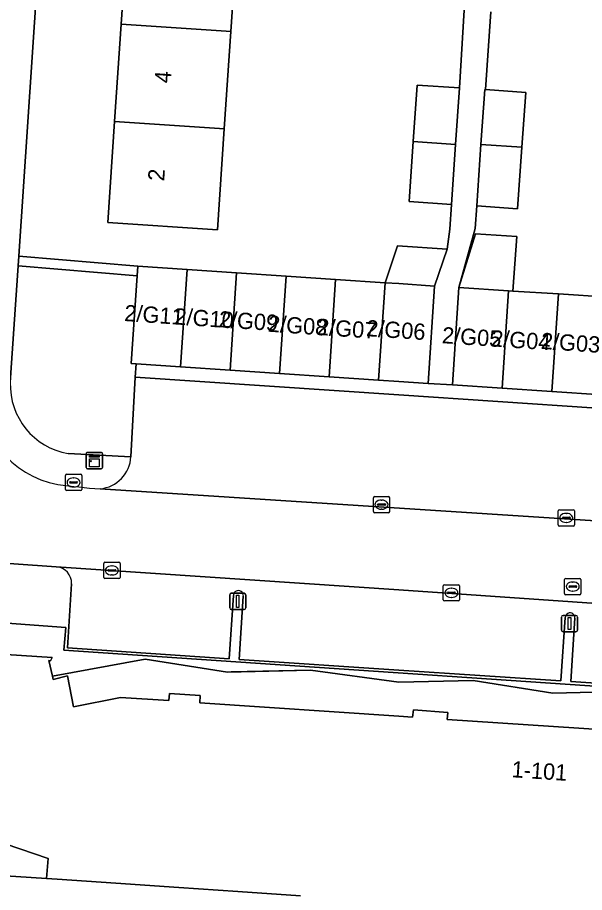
# Model space of a CAD drawing. Extents: x 161848 to 162726, y 385382 to 386521.
# Drawn here: x 161976.6 to 162011.4, y 386115.6 to 386169.4 of the extents above; entities that cross this region are included whole.
import ezdxf

# ---------------------------------------------------------------- set-up
doc = ezdxf.new("R2010")
doc.units = 0
for name, color, linetype in [('IMGEO_Erf', 7, 'Continuous'), ('IMGEO_Groenvoorziening', 7, 'Continuous'), ('IMGEO_Haag', 7, 'Continuous'), ('IMGEO_Kast', 7, 'Continuous'), ('IMGEO_Kolk', 7, 'Continuous'), ('IMGEO_Lichtmast', 7, 'Continuous'), ('IMGEO_Pand', 7, 'Continuous'), ('IMGEO_Pand_nummerreeks', 7, 'Continuous'), ('IMGEO_Pand_overbouw', 7, 'Continuous'), ('IMGEO_Parkeervlak_open', 7, 'Continuous'), ('IMGEO_Rijbaan_lokaal_open', 7, 'Continuous'), ('IMGEO_Rioolput', 7, 'Continuous'), ('IMGEO_Voetpad_open', 7, 'Continuous')]:
    doc.layers.add(name, color=color, linetype=linetype)

msp = doc.modelspace()

# ---------------------------------------------------------------- linework, layer by layer
at = {"layer": 'IMGEO_Erf'}
for points in [[(161981.585, 386228.399), (161976.646, 386154.728), (161983.951, 386154.112), (161986.99, 386153.908), (161990.03, 386153.703), (161993.069, 386153.499), (161996.108, 386153.295), (161999.148, 386153.09), (161999.91, 386155.357), (162002.957, 386155.152), (162003.129, 386156.382), (162003.232, 386157.9), (162000.629, 386158.077), (162000.88, 386161.759), (162001.117, 386165.23), (162003.72, 386165.053), (162004.011, 386169.831)], [(162005.647, 386169.739), (162005.314, 386164.953), (162007.786, 386164.781), (162007.553, 386161.42), (162007.291, 386157.629), (162004.777, 386157.804), (162004.681, 386156.415), (162003.684, 386152.798), (162004.707, 386156.103), (162007.247, 386155.936), (162006.991, 386152.581), (162009.79, 386152.398), (162012.842, 386152.199), (162015.895, 386151.999), (162018.948, 386151.799), (162023.139, 386151.525), (162033.95, 386150.87), (162035.725, 386178.438)], [(161990.074, 386174.523), (161989.672, 386168.529), (161989.271, 386162.535), (161988.856, 386156.345), (161982.121, 386156.796), (161982.536, 386162.985), (161982.937, 386168.979), (161983.339, 386174.973)]]:
    msp.add_lwpolyline(points, dxfattribs=at)
at = {"layer": 'IMGEO_Groenvoorziening'}
msp.add_lwpolyline([(161983.951, 386154.112), (161976.646, 386154.728), (161976.606, 386154.129), (161983.911, 386153.513)], close=True, dxfattribs=at)
for points in [[(161983.911, 386153.513), (161976.606, 386154.129), (161976.126, 386146.967)], [(161979.683, 386142.598), (161983.537, 386142.393), (161983.794, 386147.293), (161983.861, 386148.104), (161983.547, 386148.125), (161983.911, 386153.513)]]:
    msp.add_lwpolyline(points, dxfattribs=at)
msp.add_arc((161980.404, 386146.818), 4.281, 178.0004, 260.3007, dxfattribs=at)
at = {"layer": 'IMGEO_Haag'}
msp.add_lwpolyline([(161983.951, 386154.112), (161976.646, 386154.728), (161976.606, 386154.129), (161983.911, 386153.513)], close=True, dxfattribs=at)
at = {"layer": 'IMGEO_Kast'}
for p, q in [((161980.864, 386142.663), (161981.705, 386142.663)), ((161981.705, 386142.663), (161980.864, 386142.663)), ((161980.789, 386141.738), (161980.789, 386142.579)), ((161980.789, 386142.579), (161980.789, 386141.738)), ((161981.789, 386142.588), (161981.789, 386141.747)), ((161981.789, 386141.747), (161981.789, 386142.588)), ((161981.714, 386141.663), (161980.873, 386141.663)), ((161980.873, 386141.663), (161981.714, 386141.663))]:
    msp.add_line(p, q, dxfattribs=at)
for points in [[(161980.984, 386142.453), (161981.584, 386142.453), (161981.584, 386142.368), (161980.984, 386142.368), (161980.984, 386142.453)], [(161980.984, 386142.278), (161981.584, 386142.278), (161981.584, 386141.789), (161980.984, 386141.789), (161980.984, 386142.278)]]:
    msp.add_lwpolyline(points, dxfattribs=at)
msp.add_circle((161981.068, 386142.127), 0.0377, dxfattribs=at)
for centre, start, end in [((161980.867, 386142.585), 92.4484, 184.2845), ((161980.867, 386142.585), 92.4484, 184.2845), ((161981.711, 386142.585), 2.4484, 94.2845), ((161981.711, 386142.585), 2.4484, 94.2845), ((161980.867, 386141.741), 182.4484, 274.2845), ((161980.867, 386141.741), 182.4484, 274.2845), ((161981.711, 386141.741), 272.4484, 4.2845), ((161981.711, 386141.741), 272.4484, 4.2845)]:
    msp.add_arc(centre, 0.0779, start, end, dxfattribs=at)
at = {"layer": 'IMGEO_Kolk'}
for p, q in [((161979.513, 386140.395), (161979.513, 386141.247)), ((161979.588, 386141.321), (161980.44, 386141.321)), ((161980.001, 386141.101), (161980.026, 386141.101)), ((161980.514, 386141.247), (161980.514, 386140.395)), ((161979.772, 386140.815), (161979.772, 386140.827)), ((161980.21, 386140.778), (161979.812, 386140.778)), ((161979.815, 386140.864), (161980.213, 386140.864)), ((161980.024, 386140.541), (161979.999, 386140.541)), ((161980.256, 386140.827), (161980.256, 386140.815)), ((161980.44, 386140.321), (161979.588, 386140.321)), ((161998.428, 386139.032), (161998.428, 386139.884)), ((161998.503, 386139.958), (161999.355, 386139.958)), ((161998.687, 386139.452), (161998.687, 386139.464)), ((161998.73, 386139.501), (161999.128, 386139.501)), ((161998.916, 386139.738), (161998.941, 386139.738)), ((161999.171, 386139.464), (161999.171, 386139.452)), ((161999.429, 386139.884), (161999.429, 386139.032)), ((161999.355, 386138.958), (161998.503, 386138.958)), ((161999.125, 386139.415), (161998.727, 386139.415)), ((161998.939, 386139.178), (161998.914, 386139.178)), ((162009.778, 386138.215), (162009.778, 386139.067)), ((162009.853, 386139.141), (162010.705, 386139.141)), ((162010.266, 386138.921), (162010.291, 386138.921)), ((162010.779, 386139.067), (162010.779, 386138.215)), ((162010.037, 386138.635), (162010.037, 386138.647)), ((162010.475, 386138.598), (162010.077, 386138.598)), ((162010.08, 386138.684), (162010.478, 386138.684)), ((162010.289, 386138.361), (162010.264, 386138.361)), ((162010.521, 386138.647), (162010.521, 386138.635)), ((162010.705, 386138.141), (162009.853, 386138.141)), ((161981.866, 386134.989), (161981.866, 386135.841)), ((161981.941, 386135.915), (161982.793, 386135.915)), ((161982.354, 386135.695), (161982.379, 386135.695)), ((161982.867, 386135.841), (161982.867, 386134.989)), ((161982.125, 386135.409), (161982.125, 386135.421)), ((161982.563, 386135.372), (161982.165, 386135.372)), ((161982.168, 386135.458), (161982.566, 386135.458)), ((161982.377, 386135.135), (161982.352, 386135.135)), ((161982.609, 386135.421), (161982.609, 386135.409)), ((161982.793, 386134.915), (161981.941, 386134.915)), ((162002.721, 386133.614), (162002.721, 386134.466)), ((162002.796, 386134.54), (162003.648, 386134.54)), ((162003.023, 386134.083), (162003.421, 386134.083)), ((162003.209, 386134.32), (162003.234, 386134.32)), ((162003.722, 386134.466), (162003.722, 386133.614)), ((162003.648, 386133.54), (162002.796, 386133.54)), ((162002.98, 386134.034), (162002.98, 386134.046)), ((162003.418, 386133.997), (162003.02, 386133.997)), ((162003.232, 386133.76), (162003.207, 386133.76)), ((162003.464, 386134.046), (162003.464, 386134.034))]:
    msp.add_line(p, q, dxfattribs=at)
for points in [[(161979.513, 386140.395), (161979.513, 386141.247)], [(161979.588, 386141.321), (161980.44, 386141.321)], [(161980.514, 386141.247), (161980.514, 386140.395)], [(161980.44, 386140.321), (161979.588, 386140.321)], [(161998.428, 386139.032), (161998.428, 386139.884)], [(161998.503, 386139.958), (161999.355, 386139.958)], [(161999.429, 386139.884), (161999.429, 386139.032)], [(161999.355, 386138.958), (161998.503, 386138.958)], [(162009.778, 386138.215), (162009.778, 386139.067)], [(162009.853, 386139.141), (162010.705, 386139.141)], [(162010.779, 386139.067), (162010.779, 386138.215)], [(162010.705, 386138.141), (162009.853, 386138.141)], [(161981.866, 386134.989), (161981.866, 386135.841)], [(161981.941, 386135.915), (161982.793, 386135.915)], [(161982.867, 386135.841), (161982.867, 386134.989)], [(161982.793, 386134.915), (161981.941, 386134.915)], [(162002.721, 386133.614), (162002.721, 386134.466)], [(162002.796, 386134.54), (162003.648, 386134.54)], [(162003.722, 386134.466), (162003.722, 386133.614)], [(162003.648, 386133.54), (162002.796, 386133.54)]]:
    msp.add_lwpolyline(points, dxfattribs=at)
for centre, radius, start, end in [((161979.59, 386141.245), 0.0765, 91.552, 178.448), ((161979.59, 386141.245), 0.0765, 91.552, 178.448), ((161980.438, 386141.245), 0.0765, 1.552, 88.448), ((161980.438, 386141.245), 0.0765, 1.552, 88.448), ((161979.812, 386140.824), 0.0403, 85.8775, 175.7526), ((161979.809, 386140.814), 0.0366, 178.938, 274.7102), ((161980.213, 386140.821), 0.043, 264.8664, 352.4533), ((161980.217, 386140.826), 0.0386, 1.7309, 96.639), ((161979.59, 386140.397), 0.0765, 181.552, 268.448), ((161979.59, 386140.397), 0.0765, 181.552, 268.448), ((161980.438, 386140.397), 0.0765, 271.552, 358.448), ((161980.438, 386140.397), 0.0765, 271.552, 358.448), ((161998.505, 386139.882), 0.0765, 91.552, 178.448), ((161998.505, 386139.882), 0.0765, 91.552, 178.448), ((161998.727, 386139.461), 0.0403, 85.8775, 175.7526), ((161998.724, 386139.451), 0.0366, 178.938, 274.7102), ((161999.128, 386139.458), 0.043, 264.8664, 352.4533), ((161999.132, 386139.463), 0.0386, 1.7309, 96.639), ((161999.353, 386139.882), 0.0765, 1.552, 88.448), ((161999.353, 386139.882), 0.0765, 1.552, 88.448), ((161998.505, 386139.034), 0.0765, 181.552, 268.448), ((161998.505, 386139.034), 0.0765, 181.552, 268.448), ((161999.353, 386139.034), 0.0765, 271.552, 358.448), ((161999.353, 386139.034), 0.0765, 271.552, 358.448), ((162009.855, 386139.065), 0.0765, 91.552, 178.448), ((162009.855, 386139.065), 0.0765, 91.552, 178.448), ((162010.703, 386139.065), 0.0765, 1.552, 88.448), ((162010.703, 386139.065), 0.0765, 1.552, 88.448), ((162010.077, 386138.644), 0.0403, 85.8775, 175.7526), ((162010.074, 386138.634), 0.0366, 178.938, 274.7102), ((162010.478, 386138.641), 0.043, 264.8664, 352.4533), ((162010.482, 386138.646), 0.0386, 1.7309, 96.639), ((162009.855, 386138.217), 0.0765, 181.552, 268.448), ((162009.855, 386138.217), 0.0765, 181.552, 268.448), ((162010.703, 386138.217), 0.0765, 271.552, 358.448), ((162010.703, 386138.217), 0.0765, 271.552, 358.448), ((161981.943, 386135.839), 0.0765, 91.552, 178.448), ((161981.943, 386135.839), 0.0765, 91.552, 178.448), ((161982.791, 386135.839), 0.0765, 1.552, 88.448), ((161982.791, 386135.839), 0.0765, 1.552, 88.448), ((161982.165, 386135.418), 0.0403, 85.8775, 175.7526), ((161982.162, 386135.408), 0.0366, 178.938, 274.7102), ((161982.566, 386135.415), 0.043, 264.8664, 352.4533), ((161982.57, 386135.42), 0.0386, 1.7309, 96.639), ((161981.943, 386134.991), 0.0765, 181.552, 268.448), ((161981.943, 386134.991), 0.0765, 181.552, 268.448), ((161982.791, 386134.991), 0.0765, 271.552, 358.448), ((161982.791, 386134.991), 0.0765, 271.552, 358.448), ((162002.798, 386134.464), 0.0765, 91.552, 178.448), ((162002.798, 386134.464), 0.0765, 91.552, 178.448), ((162003.02, 386134.043), 0.0403, 85.8775, 175.7526), ((162003.425, 386134.045), 0.0386, 1.7309, 96.639), ((162003.646, 386134.464), 0.0765, 1.552, 88.448), ((162003.646, 386134.464), 0.0765, 1.552, 88.448), ((162002.798, 386133.616), 0.0765, 181.552, 268.448), ((162002.798, 386133.616), 0.0765, 181.552, 268.448), ((162003.017, 386134.033), 0.0366, 178.938, 274.7102), ((162003.421, 386134.04), 0.043, 264.8664, 352.4533), ((162003.646, 386133.616), 0.0765, 271.552, 358.448), ((162003.646, 386133.616), 0.0765, 271.552, 358.448)]:
    msp.add_arc(centre, radius, start, end, dxfattribs=at)
for centre, major_axis, ratio, start_param, end_param in [((161980, 386140.821), (-0.387, 0.002), 0.722429, 4.712389, 7.853982), ((161980.025, 386140.821), (-0.39, 0.002), 0.717154, 1.570796, 4.712389), ((161998.915, 386139.458), (-0.387, 0.002), 0.722429, 4.712389, 7.853982), ((161998.94, 386139.458), (-0.39, 0.002), 0.717154, 1.570796, 4.712389), ((162010.265, 386138.641), (-0.387, 0.002), 0.722429, 4.712389, 7.853982), ((162010.29, 386138.641), (-0.39, 0.002), 0.717154, 1.570796, 4.712389), ((161982.353, 386135.415), (-0.387, 0.002), 0.722429, 4.712389, 7.853982), ((161982.378, 386135.415), (-0.39, 0.002), 0.717154, 1.570796, 4.712389), ((162003.208, 386134.04), (-0.387, 0.002), 0.722429, 4.712389, 7.853982), ((162003.233, 386134.04), (-0.39, 0.002), 0.717154, 1.570796, 4.712389)]:
    msp.add_ellipse(centre, major_axis=major_axis, ratio=ratio, start_param=start_param, end_param=end_param, dxfattribs=at)
at = {"layer": 'IMGEO_Lichtmast'}
for p, q in [((161989.601, 386133.112), (161989.601, 386133.912)), ((161989.601, 386133.912), (161989.601, 386133.112)), ((161989.701, 386134.012), (161990.491, 386134.012)), ((161990.491, 386134.012), (161989.701, 386134.012)), ((161990.591, 386133.912), (161990.591, 386133.112)), ((161990.591, 386133.112), (161990.591, 386133.912)), ((161990.491, 386133.012), (161989.701, 386133.012)), ((161989.701, 386133.012), (161990.491, 386133.012)), ((162009.981, 386131.753), (162009.981, 386132.553)), ((162009.981, 386132.553), (162009.981, 386131.753)), ((162010.081, 386132.653), (162010.871, 386132.653)), ((162010.871, 386132.653), (162010.081, 386132.653)), ((162010.971, 386132.553), (162010.971, 386131.753)), ((162010.971, 386131.753), (162010.971, 386132.553)), ((162010.871, 386131.653), (162010.081, 386131.653)), ((162010.081, 386131.653), (162010.871, 386131.653))]:
    msp.add_line(p, q, dxfattribs=at)
for points in [[(161990.021, 386133.887), (161990.171, 386133.887), (161990.171, 386133.137), (161990.021, 386133.137), (161990.021, 386133.887)], [(162010.401, 386132.528), (162010.551, 386132.528), (162010.551, 386131.778), (162010.401, 386131.778), (162010.401, 386132.528)]]:
    msp.add_lwpolyline(points, dxfattribs=at)
for centre, start, end in [((161989.701, 386133.912), 90, 180), ((161989.701, 386133.912), 90, 180), ((161990.491, 386133.912), 0, 90), ((161990.491, 386133.912), 360, 90), ((161989.701, 386133.112), 180, 270), ((161989.701, 386133.112), 180, 270), ((161990.491, 386133.112), 270, 0), ((161990.491, 386133.112), 270, 0), ((162010.081, 386132.553), 90, 180), ((162010.081, 386132.553), 90, 180), ((162010.871, 386132.553), 0, 90), ((162010.871, 386132.553), 360, 90), ((162010.081, 386131.753), 180, 270), ((162010.081, 386131.753), 180, 270), ((162010.871, 386131.753), 270, 0), ((162010.871, 386131.753), 270, 0)]:
    msp.add_arc(centre, 0.1, start, end, dxfattribs=at)
at = {"layer": 'IMGEO_Pand'}
for points in [[(161990.074, 386174.523), (161989.785, 386174.542), (161983.339, 386174.973), (161982.937, 386168.979), (161989.384, 386168.548), (161989.672, 386168.529)], [(161989.672, 386168.529), (161989.384, 386168.548), (161982.937, 386168.979), (161982.536, 386162.985), (161988.983, 386162.554), (161989.271, 386162.535)], [(162003.72, 386165.053), (162001.117, 386165.23), (162000.88, 386161.759), (162003.483, 386161.585)], [(162007.786, 386164.781), (162005.314, 386164.953), (162005.273, 386164.956), (162005.039, 386161.586), (162007.553, 386161.42)], [(161982.121, 386156.796), (161988.856, 386156.345), (161989.271, 386162.535), (161988.983, 386162.554), (161982.536, 386162.985)], [(162000.629, 386158.077), (162003.232, 386157.9), (162003.483, 386161.585), (162000.88, 386161.759)], [(162004.777, 386157.804), (162007.291, 386157.629), (162007.553, 386161.42), (162005.039, 386161.586)], [(162003.684, 386152.798), (162006.737, 386152.598), (162006.991, 386152.581), (162007.247, 386155.936), (162004.707, 386156.103)], [(162002.957, 386155.152), (161999.91, 386155.357), (161999.148, 386153.09), (162000, 386153.033), (162002.187, 386152.886)], [(161986.99, 386153.908), (161983.951, 386154.112), (161983.911, 386153.513), (161983.547, 386148.125), (161983.861, 386148.104), (161986.588, 386147.921)], [(161989.627, 386147.716), (161990.03, 386153.703), (161986.99, 386153.908), (161986.588, 386147.921)], [(161992.666, 386147.512), (161993.069, 386153.499), (161990.03, 386153.703), (161989.627, 386147.716)], [(161995.706, 386147.308), (161996.108, 386153.295), (161993.069, 386153.499), (161992.666, 386147.512)], [(161998.745, 386147.103), (161999.148, 386153.09), (161996.108, 386153.295), (161995.706, 386147.308)], [(162000, 386147.019), (162001.784, 386146.899), (162002.187, 386152.886), (162000, 386153.033), (161999.148, 386153.09), (161998.745, 386147.103)], [(162006.345, 386146.61), (162006.737, 386152.598), (162003.684, 386152.798), (162003.291, 386146.81)], [(162009.79, 386152.398), (162006.991, 386152.581), (162006.737, 386152.598), (162006.345, 386146.61), (162009.398, 386146.41)], [(162012.451, 386146.211), (162012.842, 386152.199), (162009.79, 386152.398), (162009.398, 386146.41)]]:
    msp.add_lwpolyline(points, close=True, dxfattribs=at)
for points in [[(162016.019, 386125.397), (162002.952, 386126.258), (162003.01, 386126.683), (162000.895, 386126.859), (162000.829, 386126.41), (162000, 386126.466), (161987.761, 386127.291), (161987.782, 386127.728), (161985.895, 386127.848), (161985.868, 386127.419), (161982.891, 386127.603), (161980.007, 386127.033), (161979.635, 386128.933), (161978.766, 386128.724), (161978.718, 386128.928), (161978.498, 386129.873), (161978.602, 386129.859), (161978.696, 386130.062), (161973.325, 386130.406)], [(161971.472, 386120.101), (161978.455, 386117.717), (161978.353, 386116.485), (161978.995, 386116.442), (161982.617, 386116.198), (161986.487, 386115.937), (161990.099, 386115.693), (161993.961, 386115.433)]]:
    msp.add_lwpolyline(points, dxfattribs=at)
at = {"layer": 'IMGEO_Pand_overbouw'}
msp.add_lwpolyline([(162014.496, 386127.996), (162009.458, 386127.881), (162004.558, 386128.647), (162000, 386128.555), (161994.559, 386129.296), (161989.686, 386129.179), (161989.466, 386129.174), (161984.411, 386129.967), (161978.718, 386128.928), (161978.766, 386128.724), (161979.635, 386128.933), (161980.007, 386127.033), (161982.891, 386127.603), (161985.868, 386127.419), (161985.895, 386127.848), (161987.782, 386127.728), (161987.761, 386127.291), (162000, 386126.466), (162000.829, 386126.41), (162000.895, 386126.859), (162003.01, 386126.683), (162002.952, 386126.258), (162016.019, 386125.397)], dxfattribs=at)
at = {"layer": 'IMGEO_Parkeervlak_open'}
for points in [[(162018.222, 386144.5), (162018.24, 386144.977), (162000, 386146.203), (161983.794, 386147.293), (161983.537, 386142.393)], [(161981.65, 386140.427), (162013.34, 386138.388), (162026.967, 386137.373)], [(162031.397, 386132.045), (162000, 386134.23), (161978.945, 386135.646)], [(161979.888, 386134.586), (161979.632, 386130.657), (161989.567, 386129.99), (161989.828, 386133.871)], [(161990.44, 386133.842), (161990.177, 386129.942), (162000, 386129.286), (162009.942, 386128.623), (162010.213, 386132.526)], [(162010.808, 386132.475), (162010.557, 386128.592), (162025.944, 386127.562), (162025.917, 386127.359), (162030.314, 386127.089), (162030.432, 386131.127)]]:
    msp.add_lwpolyline(points, dxfattribs=at)
for centre, radius, start, end in [((161981.43, 386142.527), 2.111, 275.9812, 356.368), ((161978.862, 386134.622), 1.027, 357.9652, 85.3489), ((161990.135, 386133.869), 0.307, 354.9945, 179.5796), ((162010.511, 386132.508), 0.299, 353.5757, 176.6261)]:
    msp.add_arc(centre, radius, start, end, dxfattribs=at)
at = {"layer": 'IMGEO_Rijbaan_lokaal_open'}
for points in [[(161974.226, 386146.71), (161974.259, 386147.202), (161969.52, 386147.428), (161969.352, 386144.813), (161969.043, 386139.863), (161968.815, 386136.361), (161978.945, 386135.646), (162000, 386134.23), (162031.397, 386132.045), (162031.725, 386137.072), (162026.967, 386137.373), (162013.34, 386138.388)], [(162013.34, 386138.388), (161981.65, 386140.427)]]:
    msp.add_lwpolyline(points, dxfattribs=at)
for centre, radius, start, end in [((161980.069, 386146.459), 5.848, 177.5368, 259.8967), ((161984.236, 386177.567), 37.23, 261.9826, 266.0177)]:
    msp.add_arc(centre, radius, start, end, dxfattribs=at)
at = {"layer": 'IMGEO_Rioolput'}
for p, q in [((162010.175, 386133.998), (162010.175, 386134.85)), ((162010.25, 386134.924), (162011.102, 386134.924)), ((162010.663, 386134.704), (162010.688, 386134.704)), ((162011.176, 386134.85), (162011.176, 386133.998)), ((162010.434, 386134.418), (162010.434, 386134.43)), ((162010.872, 386134.381), (162010.474, 386134.381)), ((162010.477, 386134.467), (162010.875, 386134.467)), ((162010.686, 386134.144), (162010.661, 386134.144)), ((162010.918, 386134.43), (162010.918, 386134.418)), ((162011.102, 386133.924), (162010.25, 386133.924))]:
    msp.add_line(p, q, dxfattribs=at)
for points in [[(162010.175, 386133.998), (162010.175, 386134.85)], [(162010.25, 386134.924), (162011.102, 386134.924)], [(162011.176, 386134.85), (162011.176, 386133.998)], [(162011.102, 386133.924), (162010.25, 386133.924)]]:
    msp.add_lwpolyline(points, dxfattribs=at)
for centre, radius, start, end in [((162010.252, 386134.848), 0.0765, 91.552, 178.448), ((162010.252, 386134.848), 0.0765, 91.552, 178.448), ((162011.1, 386134.848), 0.0765, 1.552, 88.448), ((162011.1, 386134.848), 0.0765, 1.552, 88.448), ((162010.474, 386134.427), 0.0403, 85.8775, 175.7526), ((162010.471, 386134.417), 0.0366, 178.938, 274.7102), ((162010.875, 386134.424), 0.043, 264.8664, 352.4533), ((162010.879, 386134.429), 0.0386, 1.7309, 96.639), ((162010.252, 386134), 0.0765, 181.552, 268.448), ((162010.252, 386134), 0.0765, 181.552, 268.448), ((162011.1, 386134), 0.0765, 271.552, 358.448), ((162011.1, 386134), 0.0765, 271.552, 358.448)]:
    msp.add_arc(centre, radius, start, end, dxfattribs=at)
for centre, major_axis, ratio, start_param, end_param in [((162010.662, 386134.424), (-0.387, 0.002), 0.722429, 4.712389, 7.853982), ((162010.687, 386134.424), (-0.39, 0.002), 0.717154, 1.570796, 4.712389)]:
    msp.add_ellipse(centre, major_axis=major_axis, ratio=ratio, start_param=start_param, end_param=end_param, dxfattribs=at)
at = {"layer": 'IMGEO_Voetpad_open'}
for points in [[(161976.126, 386146.967), (161976.606, 386154.129), (161976.646, 386154.728), (161981.585, 386228.399)], [(162004.011, 386169.831), (162003.72, 386165.053), (162003.483, 386161.585), (162003.232, 386157.9), (162003.129, 386156.382), (162002.957, 386155.152), (162002.187, 386152.886), (162001.784, 386146.899), (162003.291, 386146.81), (162003.684, 386152.798), (162004.681, 386156.415), (162004.777, 386157.804), (162005.039, 386161.586), (162005.273, 386164.956), (162005.314, 386164.953), (162005.647, 386169.739)], [(161983.537, 386142.393), (161979.683, 386142.598)], [(161978.945, 386135.646), (161968.815, 386136.361), (161963.538, 386136.715), (161963.628, 386138.174), (161953.938, 386138.819), (161938.595, 386139.84), (161937.649, 386139.903)], [(161989.828, 386133.871), (161989.567, 386129.99), (161979.632, 386130.657), (161979.888, 386134.586)], [(161993.961, 386115.433), (161990.099, 386115.693), (161986.487, 386115.937), (161982.617, 386116.198), (161978.995, 386116.442), (161978.353, 386116.485), (161970.469, 386117.005), (161960.203, 386117.699), (161959.972, 386117.481), (161959.82, 386117.337), (161957.883, 386119.929), (161956.877, 386122.689), (161956.665, 386125.746), (161957.302, 386128.704), (161958.653, 386131.231), (161960.891, 386133.6), (161961.216, 386133.187), (161971.493, 386132.493), (161979.532, 386131.905), (161979.424, 386130.509), (162025.917, 386127.359), (162025.944, 386127.562), (162010.557, 386128.592), (162010.808, 386132.475)], [(162010.213, 386132.526), (162009.942, 386128.623), (162000, 386129.286), (161990.177, 386129.942), (161990.44, 386133.842)], [(162025.917, 386127.359), (161979.424, 386130.509), (161979.532, 386131.905), (161971.493, 386132.493), (161971.466, 386132.118), (161972.155, 386128.636), (161972.071, 386127.544), (161973.586, 386127.847), (161973.707, 386130.108), (161973.386, 386130.13), (161973.325, 386130.406), (161978.696, 386130.062), (161978.602, 386129.859), (161978.498, 386129.873), (161978.718, 386128.928), (161984.411, 386129.967), (161989.466, 386129.174), (161994.559, 386129.296), (162000, 386128.555), (162004.558, 386128.647), (162009.458, 386127.881), (162014.496, 386127.996)], [(162014.496, 386127.996), (162009.458, 386127.881), (162004.558, 386128.647), (162000, 386128.555), (161994.559, 386129.296), (161989.466, 386129.174), (161984.411, 386129.967), (161978.718, 386128.928), (161978.766, 386128.724), (161979.635, 386128.933), (161980.007, 386127.033), (161982.891, 386127.603), (161985.868, 386127.419), (161985.895, 386127.848), (161987.782, 386127.728), (161987.761, 386127.291), (162000, 386126.466), (162000.829, 386126.41), (162000.895, 386126.859), (162003.01, 386126.683), (162002.952, 386126.258), (162016.019, 386125.397)]]:
    msp.add_lwpolyline(points, dxfattribs=at)
for points in [[(162018.272, 386145.83), (162015.503, 386146.011), (162012.451, 386146.211), (162009.398, 386146.41), (162006.345, 386146.61), (162003.291, 386146.81), (162001.784, 386146.899), (162000, 386147.019), (161998.745, 386147.103), (161995.706, 386147.308), (161992.666, 386147.512), (161989.627, 386147.716), (161986.588, 386147.921), (161983.861, 386148.104), (161983.794, 386147.293), (162000, 386146.203), (162018.24, 386144.977)], [(161978.353, 386116.485), (161978.455, 386117.717), (161971.472, 386120.101), (161970.493, 386117.386), (161970.469, 386117.005)]]:
    msp.add_lwpolyline(points, close=True, dxfattribs=at)
for centre, radius, start, end in [((161980.404, 386146.818), 4.281, 178.0004, 260.3007), ((161980.069, 386146.459), 5.848, 177.5368, 259.8967), ((161981.43, 386142.527), 2.111, 275.9812, 356.368), ((161984.236, 386177.567), 37.23, 261.9826, 266.0177), ((161978.862, 386134.622), 1.027, 357.9652, 85.3489), ((161990.135, 386133.869), 0.307, 354.9945, 179.5796), ((162010.511, 386132.508), 0.299, 353.5757, 176.6261)]:
    msp.add_arc(centre, radius, start, end, dxfattribs=at)

# ---------------------------------------------------------------- texts
at = {"layer": 'IMGEO_Pand_nummerreeks'}
for s, rotation, p in [('4', 86.168, (161985.98, 386165.322)), ('2', 86.168, (161985.576, 386159.307)), ('2/G11', 356.0982, (161983.106, 386150.74)), ('2/G10', 356.0966, (161986.183, 386150.53)), ('2/G09', 356.0966, (161988.908, 386150.359)), ('2/G08', 356.0966, (161991.931, 386150.084)), ('2/G07', 356.0966, (161994.944, 386149.889)), ('2/G06', 356.0966, (161997.96, 386149.81)), ('2/G05', 356.0966, (162002.621, 386149.379)), ('2/G04', 356.0982, (162005.637, 386149.184)), ('2/G03', 356.0966, (162008.693, 386149.027)), ('1-101', 356.2302, (162006.895, 386122.712))]:
    msp.add_text(s, height=1, rotation=rotation, dxfattribs=at).set_placement(p)

doc.saveas('drawing.dxf')
